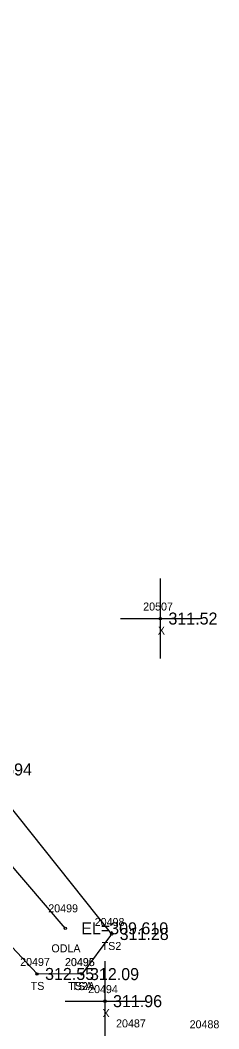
# Model space of a CAD drawing. Extents: x 1865771 to 1866867, y 910387 to 913581.
# Drawn here: x 1866220.8 to 1866245.7, y 911460.4 to 911586.4 of the extents above; entities that cross this region are included whole.
import ezdxf

# ---------------------------------------------------------------- set-up
doc = ezdxf.new("R2010")
doc.units = 0
for name, color, linetype in [('RD_DTM_BkLn2', 7, 'Continuous'), ('RD_DTM_BkLn_txCode', 7, 'Continuous'), ('RD_EX_H2O', 7, 'Continuous'), ('RD_EX_H2O_txCode', 7, 'Continuous'), ('RD_EX_Misc', 7, 'Continuous'), ('RD_EX_Misc_txCode', 7, 'Continuous'), ('RD_EX_TX_H2O_ELEV', 7, 'Continuous'), ('RD_EX_TX_Misc_ELEV', 7, 'Continuous'), ('RD_SMD_Locator', 7, 'Continuous')]:
    doc.layers.add(name, color=color, linetype=linetype)

msp = doc.modelspace()

# ---------------------------------------------------------------- linework, layer by layer
at = {"layer": 'RD_DTM_BkLn2'}
for points in [[(1866228.56, 911467.21), (1866232.27, 911472.22), (1866213.68, 911495.48), (1866165.89, 911586.25), (1866162.16, 911586.41), (1866158.86, 911583.12)], [(1866228.56, 911467.21), (1866222.94, 911467.23), (1866201.35, 911490.2), (1866158.86, 911583.12)]]:
    msp.add_lwpolyline(points, dxfattribs=at)
at = {"layer": 'RD_EX_H2O'}
msp.add_lwpolyline([(1866226.46, 911472.93), (1866209.42, 911492.78), (1866163.2, 911583.29)], dxfattribs=at)
at = {"layer": 'RD_EX_Misc'}
for p, q in [((1866238.37, 911506.64), (1866238.37, 911516.64)), ((1866233.37, 911511.64), (1866243.37, 911511.64)), ((1866231.44, 911458.83), (1866231.44, 911468.83)), ((1866226.44, 911463.83), (1866236.44, 911463.83))]:
    msp.add_line(p, q, dxfattribs=at)
at = {"layer": 'RD_SMD_Locator'}
for centre in [(1866238.37, 911511.64), (1866226.46, 911472.93), (1866232.27, 911472.22), (1866222.94, 911467.23), (1866228.56, 911467.21), (1866228.56, 911467.21), (1866231.44, 911463.83)]:
    msp.add_circle(centre, 0.15, dxfattribs=at)

# ---------------------------------------------------------------- texts
at = {"layer": 'RD_DTM_BkLn_txCode'}
for s, p in [('20498', (1866230.15, 911473.22)), ('TS2', (1866231.02, 911470.22)), ('20497', (1866220.82, 911468.23)), ('20496', (1866226.42, 911468.21)), ('20495', (1866226.44, 911468.21)), ('TS', (1866222.14, 911465.23)), ('TS2A', (1866226.83, 911465.21)), ('TSA', (1866227.27, 911465.21)), ('20487', (1866232.82, 911460.55)), ('20488', (1866242.02, 911460.44))]:
    msp.add_text(s, height=1, dxfattribs=at).set_placement(p)
at = {"layer": 'RD_EX_H2O_txCode'}
for s, p in [('20499', (1866224.34, 911474.93)), ('ODLA', (1866224.73, 911469.93))]:
    msp.add_text(s, height=1, dxfattribs=at).set_placement(p)
at = {"layer": 'RD_EX_Misc_txCode'}
for s, p in [('20507', (1866236.21, 911512.64)), ('X', (1866238.05, 911509.64)), ('20494', (1866229.32, 911464.83)), ('X', (1866231.12, 911461.83))]:
    msp.add_text(s, height=1, dxfattribs=at).set_placement(p)
at = {"layer": 'RD_EX_TX_H2O_ELEV'}
for s, p in [('EL=311.694', (1866211.42, 911492.03)), ('EL=309.610', (1866228.46, 911472.18))]:
    msp.add_text(s, height=1.5, dxfattribs=at).set_placement(p)
at = {"layer": 'RD_EX_TX_Misc_ELEV'}
for s, p in [('311.52', (1866239.37, 911510.89)), ('311.28', (1866233.27, 911471.47)), ('312.55', (1866223.94, 911466.48)), ('312.09', (1866229.56, 911466.46)), ('312.09', (1866229.56, 911466.46)), ('311.96', (1866232.44, 911463.08))]:
    msp.add_text(s, height=1.5, dxfattribs=at).set_placement(p)

doc.saveas('drawing.dxf')
